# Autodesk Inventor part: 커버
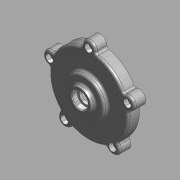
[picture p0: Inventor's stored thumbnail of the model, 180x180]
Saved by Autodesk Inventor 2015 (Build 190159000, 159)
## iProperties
Created: 2015-11
Part Number: 커버
Document SubType Name: 모델링
Designer: mdu
Material: 알루미늄 6061
Density: 1 g/cm^3
Appearance: 알루미늄 캐스트
변환 표준: STEP AP214IS
파일 이름: C:\Users\SeoGD\Desktop\?쒗뿕\而ㅻ쾭-1.stp
전처리기: Build: 253, Release: 2010 SP1 - Date: Wed 07/29/2009
전송 단위: 밀리미터
불확실성: 0.01
Author: mdu
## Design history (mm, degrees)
sketch "스케치1"
  geometry: L1 (0, 0)-(0, 26); L2 (50, 0)-(50, 15); L3 (50, 15)-(25, 15); L4 (25, 15)-(25, 21); L5 (25, 21)-(15, 21); L6 (15, 21)-(13.66, 26); L7 (13.66, 26)-(10, 26); L8 (50, 0)-(45, 0); L9 (45, 0)-(45, 10); L10 (45, 10)-(14.5, 10); L11 (14.5, 10)-(13.266, 3); L12 (13.266, 3)-(11, 3); L13 (11, 3)-(11, 16); L14 (11, 16)-(7.5, 16); L15 (7.5, 16)-(7.5, 19); L16 (7.5, 19)-(10, 19); L17 (10, 19)-(10, 26)
  constraints: 34 end point, 10 parallel, 2 perpendicular, 2 point on line, 1 vertical
  dimensions: "d11" = 100 diameter of L2 L1; "d12" = 22 diameter of L13 L1; "d13" = 90 diameter of L9 L1; "d14" = 15 distance between parallel lines of L3 L8; "d15" = 10 distance between parallel lines of L8 L10; "d16" = 29 diameter of L10.end L1; "d17" = 100 deg angle of L11 L10; "d18" = 7 distance between parallel lines of L12 L10; "d19" = 13 distance between parallel lines of L14 L12; "d20" = 3 distance between parallel lines of L16 L14; "d21" = 15 diameter of L15 L1; "d22" = 20 diameter of L17 L1; "d23" = 30 diameter of L5.end L1; "d24" = 6 distance between parallel lines of L5 L3; "d25" = 50 diameter of L4 L1; "d26" = 105 deg angle of L5 L6; "d50" = 26 distance of L1.start L1.end
revolve "회전1" sketch "스케치1" stored, may be unused: angle "d27" = 90 deg
sketch "스케치2" dims "d29" = 104
  geometry: A1 r 8.5 centre (0, 52) between (8.074, 49.344) and (-8.074, 49.344); A2 r 50 centre (0, 0) between (-8.074, 49.344) and (8.074, 49.344) reference; 2 further points
  constraints: 4 point on circle, 2 vertical alignment, 1 centre point, 1 coincident, 2 other
  dimensions: "d28" = 17 diameter of A1
extrude "돌출1" join sketch "스케치2" stored distance "d30" = 10; taper "d31" = 0 deg
fillet "모깎기3" dims "d32" = 3
fillet "모깎기4" dims "d45" = 3, "d46" = 0.2
chamfer "모따기1" distance "d47" = 1; stored, may be unused: second distance "d48" = 2, angle "d49" = 45 deg
hole "구멍2" diameter "d38" = 5.5; stored, may be unused: countersink angle "d42" = 90 deg, drill point angle "d44" = 118 deg; dims "d36" = 10, "d37" = 10, "d39" = 6, "d40" = 9.5, "d41" = 5.4, "d43" = 8
node "솔리드1"
node "솔리드 본체"
node "곡면 본체"
pattern_circular "원형 패턴1" dims angle "d34" = 360 deg
pattern_circular "원형 패턴2" dims angle "d52" = 360 deg
node "솔리드2"
